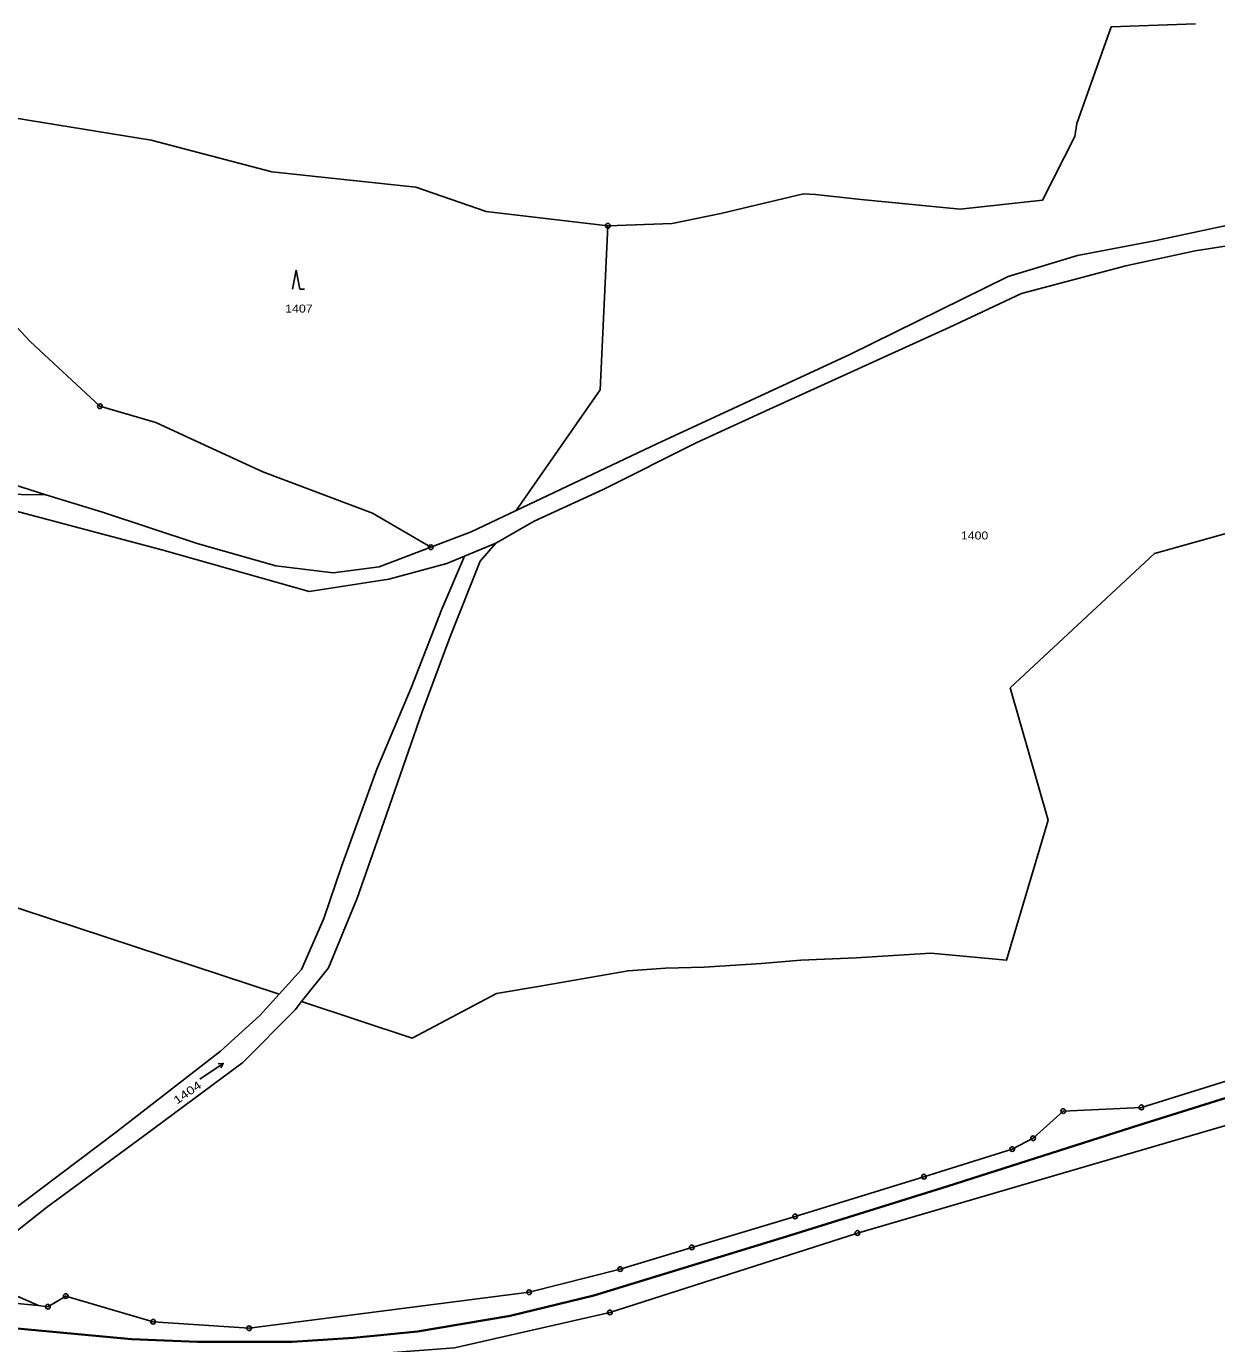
# Model space of a CAD drawing. Extents: x -872229 to -869198, y -1075981 to -1074329.
# Drawn here: x -870489.1 to -870236.3, y -1075493.1 to -1075213.2 of the extents above; entities that cross this region are included whole.
import ezdxf

# ---------------------------------------------------------------- set-up
doc = ezdxf.new("R2010")
doc.units = 0
doc.header["$LTSCALE"] = 0.68
for name, color, linetype, lineweight in [('1', 7, 'Continuous', 25), ('3', 7, 'Continuous', 25), ('6', 7, 'Continuous', 25), ('8', 7, 'Continuous', 25)]:
    doc.layers.add(name, color=color, linetype=linetype, lineweight=lineweight)
doc.layers.add('2', color=7, linetype='Continuous')

msp = doc.modelspace()

# ---------------------------------------------------------------- linework, layer by layer
at = {"layer": '1'}
for p, q in [((-870498.58, -1075312.54), (-870484.94, -1075312.75)), ((-870389.39, -1075322.98), (-870396.04, -1075325.73))]:
    msp.add_line(p, q, dxfattribs=at)
for points in [[(-870240.81, -1075212.65), (-870258.69, -1075213.29), (-870266.01, -1075233.81), (-870266.41, -1075236.59), (-870273.27, -1075250.11), (-870290.79, -1075252.03), (-870312.54, -1075249.92), (-870321.52, -1075248.92), (-870324.09, -1075248.79), (-870341.63, -1075252.94), (-870351.93, -1075255.06), (-870365.6, -1075255.58)], [(-870385.12, -1075316.07), (-870355.23, -1075301.89), (-870314.21, -1075282.93), (-870280.58, -1075266.36), (-870265.86, -1075261.9), (-870249.15, -1075258.69), (-870230, -1075254.57), (-870219.5, -1075254.87), (-870207.6, -1075253.65), (-870190, -1075251.81), (-870178.96, -1075255.5), (-870167.23, -1075255.17), (-870141.46, -1075254.46), (-870092.41, -1075254.3), (-870019.81, -1075254.06), (-869952.16, -1075254.08), (-869902.23, -1075254.21), (-869809.43, -1075253.56), (-869784.98, -1075249.67), (-869765.49, -1075244.15), (-869696.7, -1075225.43), (-869659.27, -1075213.75)], [(-870484.94, -1075312.75), (-870507.19, -1075305.67), (-870536.45, -1075296.46), (-870573.82, -1075284.57), (-870611.19, -1075272.67), (-870674.35, -1075252.89), (-870727.76, -1075235.26), (-870748.62, -1075229.44), (-870760.57, -1075227.08), (-870781.56, -1075223.68)], [(-870365.6, -1075255.58), (-870391.47, -1075252.55), (-870406.38, -1075247.4), (-870437.01, -1075244.1), (-870462.57, -1075237.4), (-870488.28, -1075233.18), (-870499.77, -1075231.3), (-870505.2, -1075231.6)], [(-870505.2, -1075231.6), (-870504.75, -1075249.5), (-870503.52, -1075255.95), (-870494.22, -1075272.65), (-870491.12, -1075277.11), (-870488.28, -1075280.14), (-870473.47, -1075293.92), (-870461.64, -1075297.33), (-870453.04, -1075301.3), (-870438.88, -1075307.81), (-870415.62, -1075316.62), (-870403.21, -1075323.85)], [(-870389.39, -1075322.98), (-870381.24, -1075318.31), (-870366.64, -1075311.61), (-870346.71, -1075301.64), (-870331.27, -1075294.54), (-870292.97, -1075277.13), (-870277.78, -1075269.99), (-870255.58, -1075264.06), (-870240.85, -1075260.92), (-870229.06, -1075259.04), (-870204.53, -1075257.8), (-870191.67, -1075256.42), (-870173.08, -1075260.11), (-870114.64, -1075257.88), (-870086.74, -1075257.68), (-870033.35, -1075257.7)], [(-870365.6, -1075255.58), (-870367.24, -1075290.43), (-870385.12, -1075316.07)], [(-870403.21, -1075323.85), (-870414.18, -1075328.04), (-870423.92, -1075329.31), (-870436.13, -1075327.84), (-870452.83, -1075323.05), (-870472.92, -1075316.43), (-870484.94, -1075312.75)], [(-870396.04, -1075325.73), (-870399.84, -1075327.3), (-870412.12, -1075330.68), (-870429.02, -1075333.26), (-870460.35, -1075324.44), (-870491.53, -1075316.1), (-870527.95, -1075326.37), (-870582.26, -1075344.32), (-870614.02, -1075355.21), (-870622.65, -1075357.15), (-870618.95, -1075358.37)], [(-870403.21, -1075323.85), (-870394.63, -1075320.58), (-870385.12, -1075316.07)], [(-870430.66, -1075420.4), (-870407.17, -1075428.14), (-870389.29, -1075418.67), (-870380.4, -1075417.19), (-870361.32, -1075413.84), (-870353.38, -1075413.31), (-870345.13, -1075413.08), (-870332.96, -1075412.32), (-870324.6, -1075411.61), (-870312.88, -1075411.08), (-870297.05, -1075410.08), (-870280.93, -1075411.62), (-870272.12, -1075381.88), (-870280.16, -1075353.72), (-870249.5, -1075325.23), (-870223.98, -1075318.04)], [(-870430.66, -1075420.4), (-870424.97, -1075413.23), (-870418.85, -1075398.4), (-870413.2, -1075382.3), (-870405.02, -1075358.84), (-870399.16, -1075343.05), (-870392.7, -1075326.81), (-870389.39, -1075322.98)], [(-870396.04, -1075325.73), (-870400.88, -1075337), (-870407.41, -1075353.74), (-870414.68, -1075371.04), (-870422.18, -1075391.71), (-870425.9, -1075402.71), (-870430.64, -1075413.55), (-870435.43, -1075418.82)], [(-870435.43, -1075418.82), (-870618.95, -1075358.37), (-870635.72, -1075362.14), (-870640.68, -1075391.97)], [(-869861.67, -1075370.56), (-869878.14, -1075367.33), (-869908.77, -1075363.47), (-869918.42, -1075363.79), (-869963.81, -1075365.31), (-869991.44, -1075371.29), (-870013.06, -1075376.14), (-870080.98, -1075397.47), (-870137.41, -1075416.91), (-870198.36, -1075434.14), (-870229.56, -1075445.28), (-870312.6, -1075469.56), (-870365.19, -1075486.42), (-870398.17, -1075493.93), (-870445.72, -1075497.57), (-870473.49, -1075498.03), (-870483.95, -1075496.85)], [(-870486.5, -1075484.99), (-870484.52, -1075485.24), (-870480.75, -1075482.95), (-870462.19, -1075488.41), (-870441.81, -1075489.8), (-870382.34, -1075482.14), (-870362.98, -1075477.23), (-870347.8, -1075472.63), (-870325.84, -1075466.04), (-870298.48, -1075457.59), (-870279.74, -1075451.72), (-870275.31, -1075449.42), (-870268.89, -1075443.67), (-870252.29, -1075442.86), (-870205.14, -1075428.17), (-870158.39, -1075411.62), (-870067.91, -1075385.07), (-870005.01, -1075365.55)], [(-870435.43, -1075418.82), (-870439.55, -1075423.36), (-870447.86, -1075430.89), (-870470, -1075448.07), (-870502.02, -1075472.23)], [(-870501.5, -1075478.06), (-870498.51, -1075474.88), (-870484.83, -1075464.11), (-870464.21, -1075448.97), (-870443.12, -1075433.33), (-870432.04, -1075422.14), (-870430.66, -1075420.4)], [(-870575.95, -1075474.7), (-870508.22, -1075480.79), (-870504.01, -1075483.3), (-870498.65, -1075483.83), (-870486.5, -1075484.99)], [(-870486.5, -1075484.99), (-870495.19, -1075481.2), (-870501.5, -1075478.06)]]:
    msp.add_lwpolyline(points, dxfattribs=at)
at = {"layer": '3'}
for p, q in [((-870431.06, -1075269.03), (-870430.064, -1075269.03)), ((-870447.294, -1075433.52), (-870447.824, -1075434.482))]:
    msp.add_line(p, q, dxfattribs=at)
for points in [[(-870431.06, -1075269.03), (-870431.81, -1075265.03), (-870432.56, -1075269.03)], [(-870452.268, -1075436.875), (-870447.294, -1075433.52), (-870448.384, -1075433.651)]]:
    msp.add_lwpolyline(points, dxfattribs=at)
at = {"layer": '6', "lineweight": 35}
for p, q in [((-870293.44, -1075459.6), (-870252.84, -1075446.64)), ((-870386.38, -1075487.12), (-870368.62, -1075482.81)), ((-870432.68, -1075492.68), (-870419.66, -1075491.85))]:
    msp.add_line(p, q, dxfattribs=at)
for points in [[(-870252.84, -1075446.64), (-870219.18, -1075436.13), (-870135.1, -1075409.54)], [(-870368.62, -1075482.81), (-870326.75, -1075470.04), (-870293.44, -1075459.6)], [(-870551.39, -1075483.38), (-870498.7, -1075489.12), (-870466.81, -1075492.11)], [(-870419.66, -1075491.85), (-870406.04, -1075490.5), (-870386.38, -1075487.12)], [(-870466.81, -1075492.11), (-870452.79, -1075492.7), (-870432.68, -1075492.68)]]:
    msp.add_lwpolyline(points, dxfattribs=at)
at = {"layer": '8'}
for centre, radius in [((-870365.6, -1075255.5799), 0.5), ((-870365.6, -1075255.5799), 0.0303), ((-870473.47, -1075293.9199), 0.5), ((-870473.47, -1075293.9199), 0.0303), ((-870403.21, -1075323.8499), 0.5), ((-870403.21, -1075323.8499), 0.0303), ((-870252.29, -1075442.8599), 0.5), ((-870268.89, -1075443.6699), 0.5), ((-870268.89, -1075443.6699), 0.0303), ((-870252.29, -1075442.8599), 0.0303), ((-870275.31, -1075449.4199), 0.5), ((-870275.31, -1075449.4199), 0.0303), ((-870279.74, -1075451.7199), 0.5), ((-870279.74, -1075451.7199), 0.0303), ((-870298.48, -1075457.5899), 0.5), ((-870298.48, -1075457.5899), 0.0303), ((-870325.84, -1075466.0399), 0.5), ((-870325.84, -1075466.0399), 0.0303), ((-870312.6, -1075469.5599), 0.5), ((-870312.6, -1075469.5599), 0.0303), ((-870347.8, -1075472.6299), 0.5), ((-870347.8, -1075472.6299), 0.0303), ((-870362.98, -1075477.2299), 0.5), ((-870362.98, -1075477.2299), 0.0303), ((-870382.34, -1075482.1399), 0.5), ((-870480.75, -1075482.9499), 0.5), ((-870480.75, -1075482.9499), 0.0303), ((-870382.34, -1075482.1399), 0.0303), ((-870484.52, -1075485.2399), 0.5), ((-870484.52, -1075485.2399), 0.0303), ((-870365.19, -1075486.4199), 0.5), ((-870365.19, -1075486.4199), 0.0303), ((-870462.19, -1075488.4099), 0.5), ((-870462.19, -1075488.4099), 0.0303), ((-870441.81, -1075489.7999), 0.5), ((-870441.81, -1075489.7999), 0.0303)]:
    msp.add_circle(centre, radius, dxfattribs=at)

# ---------------------------------------------------------------- texts
at = {"layer": '2', "width": 1.15}
for s, p in [('1407', (-870434.13, -1075274.01)), ('1400', (-870290.63, -1075322.22))]:
    msp.add_text(s, height=1.7, dxfattribs=at).set_placement(p)
at = {"layer": '2', "width": 1.3}
msp.add_text('1404', height=1.7, rotation=35, dxfattribs=at).set_placement((-870457.132, -1075442.306))

doc.saveas('drawing.dxf')
